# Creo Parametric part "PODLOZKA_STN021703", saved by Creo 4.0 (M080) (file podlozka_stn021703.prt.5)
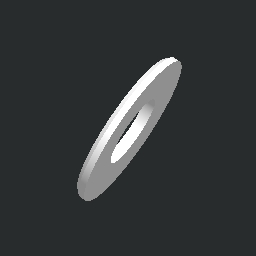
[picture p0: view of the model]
Units: Custom; MM, KILOGRAM, SECS
Materials in the file: OCEL_N

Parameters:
  KATEGORIE = "4"
  NAZOV = "PODLOZKA_STN021703"
  NORMA = "STN 02 1703"
  N1 = "ST"
  N2 = "T"
  NAZOV_1 = "START_PART_IPM"
  PTC_MATERIAL_NAME = "OCEL_N"

Other parameters: HMOTNOST, HUSTOTA, HMOTNOST_1, D3

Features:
  1. chamfer

Layers: BEZUGSACHSEN, BOHRUNGEN, KONSTRUKTIONSELEMENTE, NORMTEILE

Family table entries: GENERIC, PODLOZKA_3_2, PODLOZKA_STN021703, value(d_val), value(i_val), PODLOZKA_4_3, PODLOZKA_STN021703, 2/ , PODLOZKA_5_3, PODLOZKA_STN021703, 2/#, PODLOZKA_6_4, PODLOZKA_STN021703, 2/&, PODLOZKA_8_4, PODLOZKA_STN021703, 2/,, PODLOZKA_10_5, PODLOZKA_STN021703, !/%, 2/2, PODLOZKA_13, PODLOZKA_STN021703, !/*, 2/4, PODLOZKA_17, PODLOZKA_STN021703, !/1, 2/;, PODLOZKA_21, PODLOZKA_STN021703, !/5, # Pro/TABLE, [] S 92;, [] W 10;, [A] W  3;, [B] W 14;, [C] W 10;, [D] W 10;, [E] W 10;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

Surfaces: 2 plane, 2 cylinder, 2 cone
